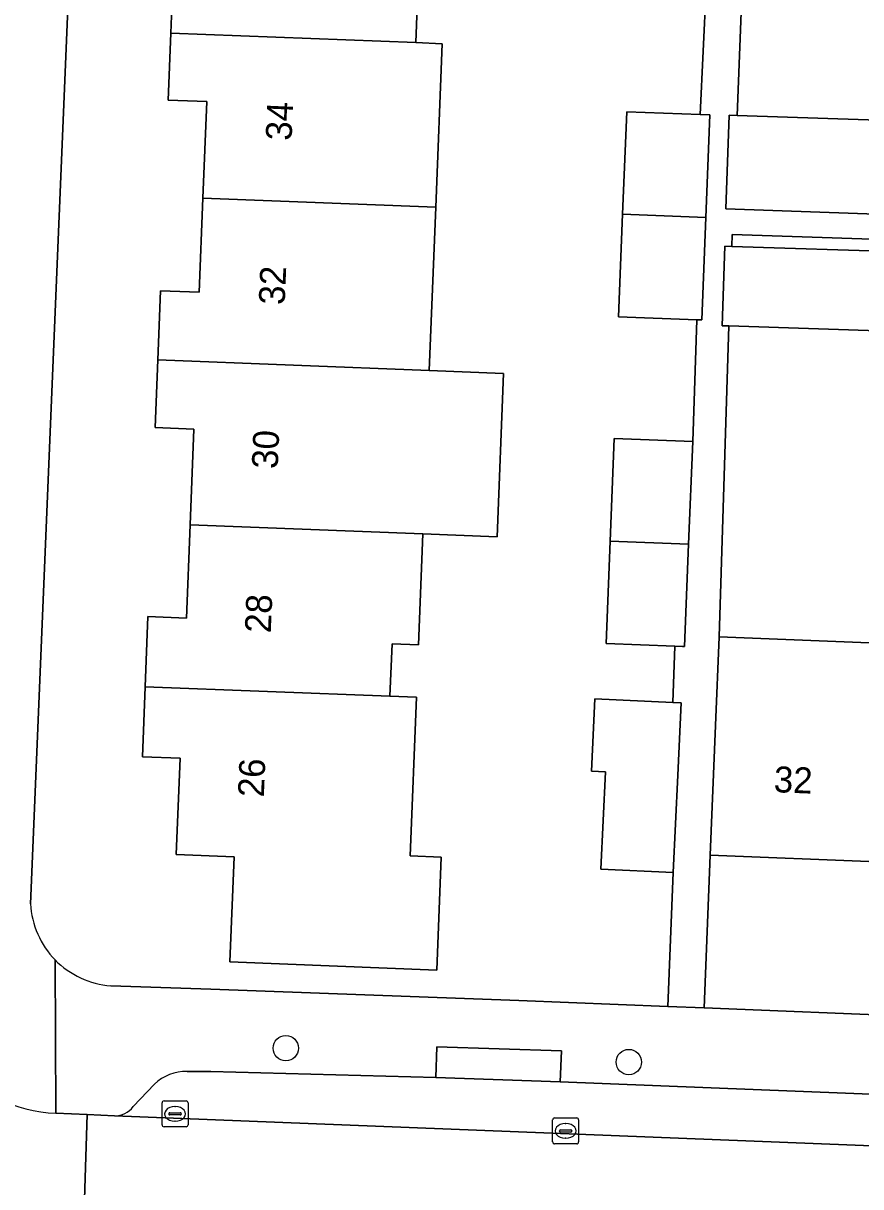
# Model space of a CAD drawing. Extents: x 160732 to 162107, y 387428 to 388479.
# Drawn here: x 161270.14 to 161302.41, y 387617.33 to 387662.13 of the extents above; entities that cross this region are included whole.
import ezdxf

# ---------------------------------------------------------------- set-up
doc = ezdxf.new("R2010")
doc.units = 0
for name, color, linetype in [('IMGEO_Boom', 7, 'Continuous'), ('IMGEO_Erf', 7, 'Continuous'), ('IMGEO_Kolk', 7, 'Continuous'), ('IMGEO_Pand', 7, 'Continuous'), ('IMGEO_Pand_nummerreeks', 7, 'Continuous'), ('IMGEO_Parkeervlak_open', 7, 'Continuous'), ('IMGEO_Rijbaan_lokaal_open', 7, 'Continuous'), ('IMGEO_Voetpad_open', 7, 'Continuous')]:
    doc.layers.add(name, color=color, linetype=linetype)

msp = doc.modelspace()

# ---------------------------------------------------------------- linework, layer by layer
at = {"layer": 'IMGEO_Boom'}
for centre in [(161280.258, 387622.661), (161293.474, 387622.126)]:
    msp.add_circle(centre, 0.489, dxfattribs=at)
at = {"layer": 'IMGEO_Erf'}
for points in [[(161293.238, 387654.774), (161293.395, 387658.724), (161296.229, 387658.614), (161296.454, 387663.509), (161293.621, 387663.619), (161293.769, 387667.357), (161293.925, 387671.308), (161296.694, 387671.201), (161296.939, 387676.213), (161294.25, 387676.306), (161294.384, 387680.17), (161297.073, 387680.076), (161297.191, 387683.116), (161275.521, 387683.956)], [(161351.796, 387680.997), (161298.599, 387683.061), (161297.649, 387658.584), (161304.248, 387658.357)], [(161272.627, 387681.201), (161270.423, 387628.225)], [(161285.348, 387663.446), (161285.266, 387661.386), (161286.284, 387661.346), (161286.036, 387655.053), (161285.787, 387648.76), (161288.647, 387648.649), (161288.399, 387642.357), (161285.539, 387642.468), (161285.37, 387638.195), (161284.351, 387638.235), (161284.271, 387636.215), (161285.29, 387636.175), (161285.049, 387630.063), (161286.251, 387630.015), (161286.08, 387625.668), (161278.106, 387625.983), (161278.265, 387630.029), (161276.036, 387630.116), (161276.183, 387633.83), (161274.731, 387633.887), (161274.837, 387636.581), (161274.944, 387639.284), (161276.429, 387639.226), (161276.571, 387642.816), (161276.716, 387646.5), (161275.227, 387646.559), (161275.33, 387649.166), (161275.435, 387651.834), (161276.923, 387651.775), (161277.066, 387655.401), (161277.212, 387659.115), (161275.728, 387659.174), (161275.83, 387661.752), (161275.936, 387664.431)], [(161273.516, 387625.067), (161277.368, 387624.929), (161289.236, 387624.502), (161294.978, 387624.268), (161295.188, 387629.43), (161292.4, 387629.559), (161292.574, 387633.308), (161292.038, 387633.333), (161292.168, 387636.114), (161295.166, 387635.974), (161295.251, 387638.142), (161292.598, 387638.245), (161292.753, 387642.188), (161292.909, 387646.139), (161295.937, 387646.021), (161296.093, 387650.713), (161293.082, 387650.83), (161293.238, 387654.774)], [(161305.535, 387653.723), (161297.456, 387654.002), (161297.44, 387653.54), (161303.982, 387653.332)], [(161303.859, 387650.267), (161297.335, 387650.476), (161296.952, 387638.508), (161303.379, 387638.251)]]:
    msp.add_lwpolyline(points, dxfattribs=at)
msp.add_lwpolyline([(161397.784, 387626.046), (161391.357, 387626.303), (161385.049, 387626.556), (161378.741, 387626.809), (161372.432, 387627.061), (161366.124, 387627.314), (161359.816, 387627.566), (161353.508, 387627.819), (161347.2, 387628.071), (161340.892, 387628.324), (161334.584, 387628.577), (161328.275, 387628.829), (161321.967, 387629.082), (161315.659, 387629.334), (161309.351, 387629.587), (161303.043, 387629.84), (161296.615, 387630.097), (161296.376, 387624.211), (161394.861, 387620.206), (161397.417, 387620.182), (161397.549, 387620.176)], close=True, dxfattribs=at)
for centre, radius, start, end in [((161273.76, 387628.398), 3.342, 182.9758, 224.3829), ((161273.757, 387628.397), 3.339, 224.3989, 265.8544)]:
    msp.add_arc(centre, radius, start, end, dxfattribs=at)
at = {"layer": 'IMGEO_Kolk'}
for p, q in [((161275.491, 387619.707), (161275.491, 387620.559)), ((161275.566, 387620.633), (161276.418, 387620.633)), ((161276.492, 387620.559), (161276.492, 387619.707)), ((161275.75, 387620.127), (161275.75, 387620.139)), ((161276.188, 387620.09), (161275.79, 387620.09)), ((161275.793, 387620.176), (161276.191, 387620.176)), ((161275.979, 387620.413), (161276.004, 387620.413)), ((161276.234, 387620.139), (161276.234, 387620.127)), ((161276.418, 387619.633), (161275.566, 387619.633)), ((161276.002, 387619.853), (161275.977, 387619.853)), ((161290.541, 387619.049), (161290.541, 387619.901)), ((161290.616, 387619.975), (161291.468, 387619.975)), ((161291.029, 387619.755), (161291.054, 387619.755)), ((161291.542, 387619.901), (161291.542, 387619.049)), ((161290.8, 387619.469), (161290.8, 387619.481)), ((161291.238, 387619.432), (161290.84, 387619.432)), ((161290.843, 387619.518), (161291.241, 387619.518)), ((161291.052, 387619.195), (161291.027, 387619.195)), ((161291.284, 387619.481), (161291.284, 387619.469)), ((161291.468, 387618.975), (161290.616, 387618.975))]:
    msp.add_line(p, q, dxfattribs=at)
for points in [[(161275.491, 387619.707), (161275.491, 387620.559)], [(161275.566, 387620.633), (161276.418, 387620.633)], [(161276.492, 387620.559), (161276.492, 387619.707)], [(161276.418, 387619.633), (161275.566, 387619.633)], [(161290.541, 387619.049), (161290.541, 387619.901)], [(161290.616, 387619.975), (161291.468, 387619.975)], [(161291.542, 387619.901), (161291.542, 387619.049)], [(161291.468, 387618.975), (161290.616, 387618.975)]]:
    msp.add_lwpolyline(points, dxfattribs=at)
for centre, radius, start, end in [((161275.568, 387620.557), 0.0765, 91.552, 178.448), ((161275.568, 387620.557), 0.0765, 91.552, 178.448), ((161276.416, 387620.557), 0.0765, 1.552, 88.448), ((161276.416, 387620.557), 0.0765, 1.552, 88.448), ((161275.79, 387620.136), 0.0403, 85.8775, 175.7526), ((161275.787, 387620.126), 0.0366, 178.938, 274.7102), ((161276.191, 387620.133), 0.043, 264.8664, 352.4533), ((161276.195, 387620.138), 0.0386, 1.7309, 96.639), ((161275.568, 387619.709), 0.0765, 181.552, 268.448), ((161275.568, 387619.709), 0.0765, 181.552, 268.448), ((161276.416, 387619.709), 0.0765, 271.552, 358.448), ((161276.416, 387619.709), 0.0765, 271.552, 358.448), ((161290.618, 387619.899), 0.0765, 91.552, 178.448), ((161290.618, 387619.899), 0.0765, 91.552, 178.448), ((161291.466, 387619.899), 0.0765, 1.552, 88.448), ((161291.466, 387619.899), 0.0765, 1.552, 88.448), ((161290.84, 387619.478), 0.0403, 85.8775, 175.7526), ((161290.837, 387619.468), 0.0366, 178.938, 274.7102), ((161291.241, 387619.475), 0.043, 264.8664, 352.4533), ((161291.245, 387619.48), 0.0386, 1.7309, 96.639), ((161290.618, 387619.051), 0.0765, 181.552, 268.448), ((161290.618, 387619.051), 0.0765, 181.552, 268.448), ((161291.466, 387619.051), 0.0765, 271.552, 358.448), ((161291.466, 387619.051), 0.0765, 271.552, 358.448)]:
    msp.add_arc(centre, radius, start, end, dxfattribs=at)
for centre, major_axis, ratio, start_param, end_param in [((161275.978, 387620.133), (-0.387, 0.002), 0.722429, 4.712389, 7.853982), ((161276.003, 387620.133), (-0.39, 0.002), 0.717154, 1.570796, 4.712389), ((161291.028, 387619.475), (-0.387, 0.002), 0.722429, 4.712389, 7.853982), ((161291.053, 387619.475), (-0.39, 0.002), 0.717154, 1.570796, 4.712389)]:
    msp.add_ellipse(centre, major_axis=major_axis, ratio=ratio, start_param=start_param, end_param=end_param, dxfattribs=at)
at = {"layer": 'IMGEO_Pand'}
for points in [[(161286.533, 387667.638), (161277.616, 387667.984), (161277.473, 387664.371), (161275.936, 387664.431), (161275.83, 387661.752), (161285.266, 387661.386), (161285.348, 387663.446), (161286.365, 387663.406)], [(161286.284, 387661.346), (161285.266, 387661.386), (161275.83, 387661.752), (161275.728, 387659.174), (161277.212, 387659.115), (161277.066, 387655.401), (161286.036, 387655.053)], [(161296.229, 387658.614), (161293.395, 387658.724), (161293.238, 387654.774), (161296.44, 387654.649), (161296.597, 387658.6)], [(161304.248, 387658.357), (161297.649, 387658.584), (161297.336, 387658.595), (161297.212, 387654.985), (161304.104, 387654.747)], [(161285.787, 387648.76), (161286.036, 387655.053), (161277.066, 387655.401), (161276.923, 387651.775), (161275.435, 387651.834), (161275.33, 387649.166)], [(161296.44, 387654.649), (161293.238, 387654.774), (161293.082, 387650.83), (161296.093, 387650.713), (161296.284, 387650.706)], [(161303.982, 387653.332), (161297.44, 387653.54), (161297.169, 387653.549), (161297.071, 387650.484), (161297.335, 387650.476), (161303.859, 387650.267)], [(161285.787, 387648.76), (161275.33, 387649.166), (161275.227, 387646.559), (161276.716, 387646.5), (161276.571, 387642.816), (161285.539, 387642.468), (161288.399, 387642.357), (161288.647, 387648.649)], [(161295.937, 387646.021), (161292.909, 387646.139), (161292.753, 387642.188), (161295.781, 387642.07)], [(161285.539, 387642.468), (161276.571, 387642.816), (161276.429, 387639.226), (161274.944, 387639.284), (161274.837, 387636.581), (161284.271, 387636.215), (161284.351, 387638.235), (161285.37, 387638.195)], [(161295.781, 387642.07), (161292.753, 387642.188), (161292.598, 387638.245), (161295.251, 387638.142), (161295.541, 387638.131), (161295.625, 387638.128)], [(161303.374, 387638.122), (161303.379, 387638.251), (161296.952, 387638.508), (161296.815, 387635.093), (161296.615, 387630.097), (161303.043, 387629.84)], [(161285.29, 387636.175), (161284.271, 387636.215), (161274.837, 387636.581), (161274.731, 387633.887), (161276.183, 387633.83), (161276.036, 387630.116), (161278.265, 387630.029), (161278.106, 387625.983), (161286.08, 387625.668), (161286.251, 387630.015), (161285.049, 387630.063)], [(161295.362, 387633.178), (161295.491, 387635.959), (161295.166, 387635.974), (161292.168, 387636.114), (161292.038, 387633.333), (161292.574, 387633.308), (161292.4, 387629.559), (161295.188, 387629.43)]]:
    msp.add_lwpolyline(points, close=True, dxfattribs=at)
at = {"layer": 'IMGEO_Parkeervlak_open'}
for points in [[(161290.826, 387621.371), (161286.039, 387621.528), (161277.37, 387621.762), (161276.454, 387621.763)], [(161275.195, 387621.278), (161274.379, 387620.409)], [(161418.868, 387616.287), (161290.826, 387621.371)], [(161273.653, 387620.056), (161343.386, 387617.292), (161346.839, 387617.155), (161408.113, 387614.711), (161411.581, 387614.585), (161422.245, 387614.14)]]:
    msp.add_lwpolyline(points, dxfattribs=at)
for centre, radius, start, end in [((161276.413, 387619.994), 1.77, 88.6616, 133.4744), ((161273.657, 387620.97), 0.914, 269.7322, 322.1282)]:
    msp.add_arc(centre, radius, start, end, dxfattribs=at)
at = {"layer": 'IMGEO_Rijbaan_lokaal_open'}
for points in [[(161272.605, 387620.102), (161271.401, 387620.155)], [(161271.428, 387615.232), (161272.446, 387615.211), (161272.605, 387620.102)]]:
    msp.add_lwpolyline(points, dxfattribs=at)
msp.add_lwpolyline([(161273.653, 387620.056), (161272.605, 387620.102), (161272.446, 387615.211), (161289.172, 387614.484), (161312.936, 387613.577), (161343.203, 387612.394), (161343.386, 387617.292)], close=True, dxfattribs=at)
msp.add_arc((161271.657, 387625.97), 5.821, 178.3942, 267.4767, dxfattribs=at)
at = {"layer": 'IMGEO_Voetpad_open'}
for points in [[(161304.104, 387654.747), (161297.212, 387654.985), (161297.336, 387658.595), (161297.649, 387658.584), (161298.599, 387683.061)], [(161270.423, 387628.225), (161272.627, 387681.201)], [(161296.454, 387663.509), (161296.229, 387658.614), (161296.597, 387658.6), (161296.44, 387654.649), (161296.284, 387650.706), (161296.093, 387650.713), (161295.937, 387646.021), (161295.781, 387642.07), (161295.625, 387638.128), (161295.541, 387638.131), (161295.251, 387638.142), (161295.166, 387635.974), (161295.491, 387635.959), (161295.362, 387633.178), (161295.188, 387629.43), (161294.978, 387624.268), (161296.376, 387624.211), (161296.615, 387630.097), (161296.815, 387635.093), (161296.952, 387638.508), (161297.335, 387650.476), (161297.071, 387650.484), (161297.169, 387653.549), (161297.44, 387653.54), (161297.456, 387654.002), (161305.535, 387653.723)], [(161271.372, 387626.061), (161271.401, 387620.155), (161272.605, 387620.102), (161273.653, 387620.056)], [(161271.401, 387620.155), (161271.372, 387626.061)], [(161421.33, 387619.212), (161419, 387619.277), (161398.822, 387620.123), (161397.549, 387620.176), (161397.417, 387620.182), (161394.861, 387620.206), (161296.376, 387624.211), (161294.978, 387624.268), (161289.236, 387624.502), (161277.368, 387624.929), (161273.516, 387625.067)], [(161276.454, 387621.763), (161277.37, 387621.762), (161286.039, 387621.528), (161286.077, 387622.715), (161290.881, 387622.56), (161290.826, 387621.371), (161418.868, 387616.287)], [(161274.379, 387620.409), (161275.195, 387621.278)]]:
    msp.add_lwpolyline(points, dxfattribs=at)
msp.add_lwpolyline([(161286.039, 387621.528), (161290.826, 387621.371), (161290.881, 387622.56), (161286.077, 387622.715)], close=True, dxfattribs=at)
for centre, radius, start, end in [((161273.76, 387628.398), 3.342, 182.9758, 224.3829), ((161271.657, 387625.97), 5.821, 178.3942, 267.4767), ((161273.757, 387628.397), 3.339, 224.3989, 265.8544), ((161276.413, 387619.994), 1.77, 88.6616, 133.4744), ((161273.657, 387620.97), 0.914, 269.7322, 322.1282)]:
    msp.add_arc(centre, radius, start, end, dxfattribs=at)

# ---------------------------------------------------------------- texts
at = {"layer": 'IMGEO_Pand_nummerreeks'}
for s, rotation, p in [('34', 87.5766, (161280.48, 387657.598)), ('32', 87.5792, (161280.214, 387651.275)), ('30', 87.5766, (161279.946, 387644.958)), ('28', 87.5766, (161279.678, 387638.637)), ('26', 87.5766, (161279.411, 387632.312)), ('32', 357.707, (161299.049, 387632.522))]:
    msp.add_text(s, height=1, rotation=rotation, dxfattribs=at).set_placement(p)

doc.saveas('drawing.dxf')
